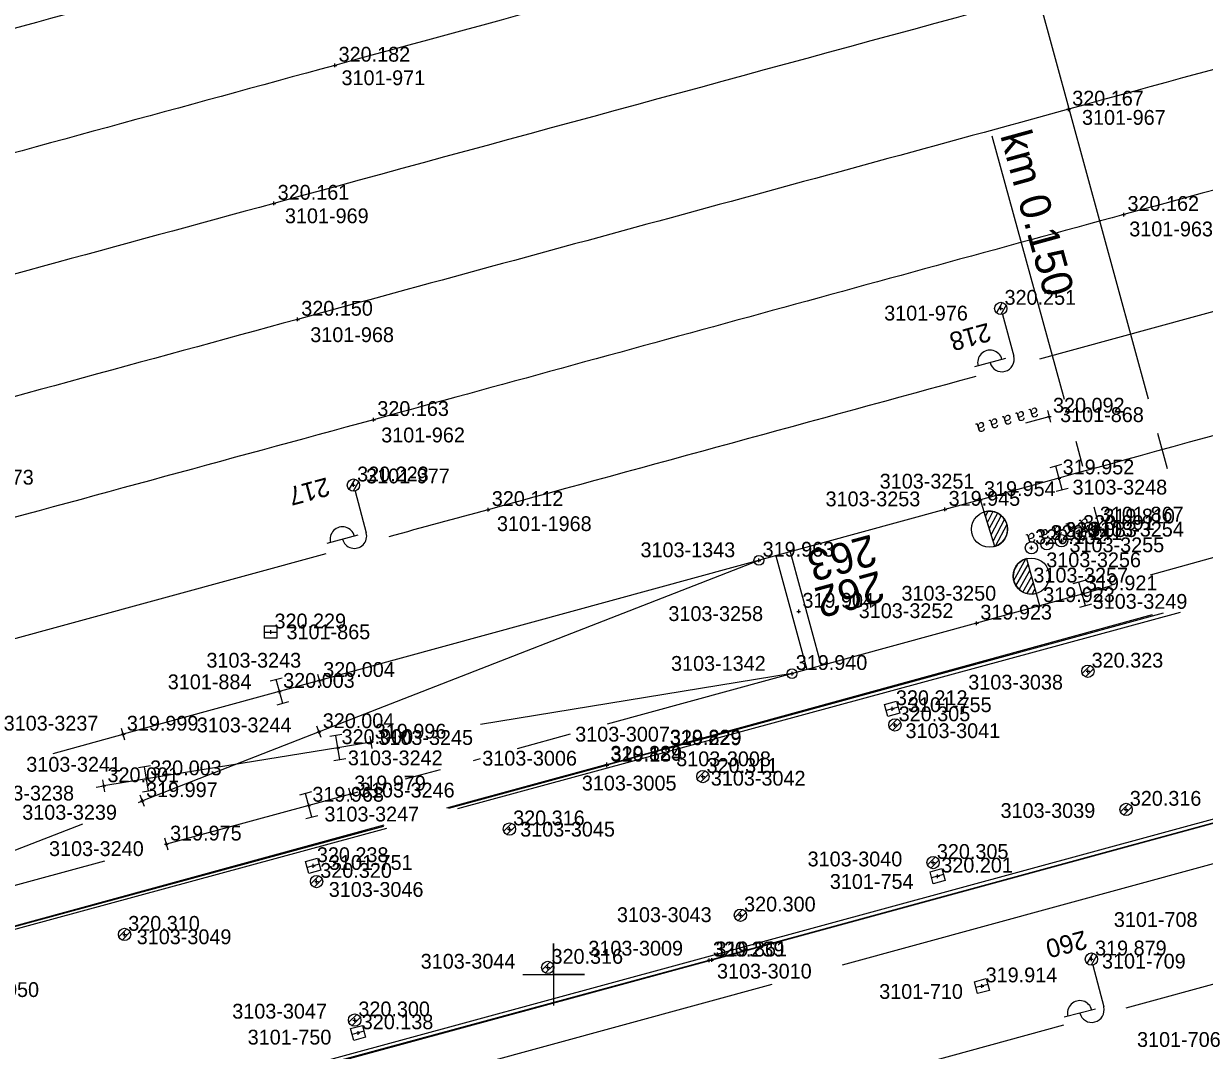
# Model space of a CAD drawing. Extents: x -821875 to -821475, y -1070280 to -1069975.
# Drawn here: x -821621.48 to -821573.63, y -1070203.07 to -1070161.48 of the extents above; entities that cross this region are included whole.
import ezdxf

# ---------------------------------------------------------------- set-up
doc = ezdxf.new("R2010")
doc.units = 0
for name, color, linetype in [('Vrstva 1', 7, 'Continuous'), ('Vrstva 11', 7, 'Continuous'), ('Vrstva 14', 7, 'Continuous'), ('Vrstva 2', 7, 'Continuous'), ('Vrstva 25', 7, 'Continuous'), ('Vrstva 28', 7, 'Continuous'), ('Vrstva 3', 7, 'Continuous'), ('Vrstva 36', 7, 'Continuous'), ('Vrstva 43', 7, 'Continuous'), ('Vrstva 6', 7, 'Continuous'), ('Vrstva 60', 7, 'Continuous'), ('Vrstva 61', 7, 'Continuous'), ('Vrstva 7', 7, 'Continuous')]:
    doc.layers.add(name, color=color, linetype=linetype)

# ---------------------------------------------------------------- blocks, each defined once
blk = doc.blocks.new('BOD')
at = {"layer": 'Vrstva 3'}
for p, q in [((-0.15, 0), (0.15, 0)), ((0, -0.15), (0, 0.15))]:
    blk.add_line(p, q, dxfattribs=at)

msp = doc.modelspace()

# ---------------------------------------------------------------- linework, layer by layer
at = {"layer": 'Vrstva 1'}
for p, q in [((-821556.332, -1070168.522), (-821580.315, -1070175.074)), ((-821609.224, -1070182.961), (-821633.113, -1070189.465)), ((-821577.392, -1070184.259), (-821578.582, -1070184.587)), ((-821552.91, -1070194.831), (-821576.812, -1070201.363)), ((-821579.336, -1070202.053), (-821600.342, -1070207.794))]:
    msp.add_line(p, q, dxfattribs=at)
for points in [[(-821579.522, -1070179.891), (-821582.708, -1070180.77)], [(-821578.582, -1070184.587), (-821580.31, -1070185.065)], [(-821609.487, -1070188.094), (-821617.444, -1070190.271)], [(-821547.636, -1070188.511), (-821567.889, -1070194.046), (-821588.306, -1070199.621)], [(-821609.506, -1070190.171), (-821616.664, -1070192.965)], [(-821607.396, -1070190.595), (-821608.744, -1070190.817), (-821616.5, -1070192.079), (-821618.229, -1070192.359)], [(-821608.229, -1070192.695), (-821609.926, -1070193.15), (-821615.692, -1070194.722)], [(-821601.25, -1070200), (-821600, -1070200), (-821600, -1070198.75), (-821600, -1070200), (-821598.75, -1070200), (-821600, -1070200), (-821600, -1070201.25)], [(-821591.155, -1070200.399), (-821624.302, -1070209.451)]]:
    msp.add_lwpolyline(points, dxfattribs=at)
for points in [[(-821515.135, -1070116.801), (-821528.933, -1070119.148), (-821545.007, -1070122.191), (-821565.452, -1070126.847), (-821593.911, -1070134.524), (-821616.729, -1070140.773), (-821646.681, -1070148.977), (-821681.98, -1070158.691), (-821694.065, -1070162.076), (-821706.535, -1070165.88), (-821718.507, -1070169.937)], [(-821540.596, -1070125.428), (-821552.18, -1070128.307), (-821562.458, -1070130.974), (-821571.2, -1070133.262), (-821591.887, -1070138.848), (-821628.102, -1070148.713), (-821679.285, -1070162.663)], [(-821540.784, -1070127.42), (-821561.358, -1070134.748), (-821573.215, -1070138.464), (-821586.824, -1070142.326), (-821602.341, -1070146.553), (-821645.37, -1070158.257), (-821677.113, -1070166.912)], [(-821500, -1070129.211), (-821517.764, -1070133.43), (-821543.081, -1070140.233), (-821582.867, -1070151.05), (-821612.032, -1070158.997), (-821647.71, -1070168.745)], [(-821500, -1070134.157), (-821525.227, -1070140.424), (-821545.665, -1070145.962), (-821584.89, -1070156.649), (-821608.863, -1070163.173), (-821645.742, -1070173.228), (-821684.141, -1070183.689)], [(-821500, -1070139.002), (-821505.719, -1070140.359), (-821526.796, -1070145.75), (-821547.362, -1070151.333), (-821583.687, -1070161.245), (-821611.332, -1070168.765), (-821648.899, -1070179.006), (-821680.4, -1070187.609), (-821711.133, -1070195.974)], [(-821500, -1070143.947), (-821500.602, -1070144.082), (-821526.98, -1070150.62), (-821544.477, -1070155.432), (-821558.026, -1070159.151), (-821579.135, -1070164.951), (-821610.376, -1070173.463), (-821647.463, -1070183.595), (-821678.921, -1070192.191), (-821710.276, -1070200.761)], [(-821500, -1070148.817), (-821511.77, -1070151.622), (-821530.609, -1070156.564), (-821556.604, -1070163.701), (-821576.895, -1070169.217), (-821607.294, -1070177.525), (-821643.435, -1070187.343), (-821669.656, -1070194.488)], [(-821500, -1070158.612), (-821502.104, -1070159.113), (-821527.988, -1070165.772), (-821558.427, -1070174.094), (-821579.522, -1070179.891)], [(-821582.886, -1070175.776), (-821602.655, -1070181.171), (-821606.681, -1070182.268)], [(-821558.309, -1070178.995), (-821560.253, -1070179.53), (-821575.821, -1070183.825)]]:
    msp.add_spline(points, degree=3, dxfattribs=at)
at = {"layer": 'Vrstva 11'}
for p, q in [((-821583.56, -1070148.661), (-821575.906, -1070176.676)), ((-821575.525, -1070178.071), (-821575.135, -1070179.497))]:
    msp.add_line(p, q, dxfattribs=at)
at = {"layer": 'Vrstva 14'}
for p, q in [((-821574.615, -1070185.337), (-821603.891, -1070193.295)), ((-821575.743, -1070185.432), (-821595.438, -1070190.834)), ((-821595.436, -1070190.859), (-821575.284, -1070185.343)), ((-821626.102, -1070208.071), (-821552.45, -1070188.031)), ((-821597.846, -1070191.49), (-821595.438, -1070190.834)), ((-821595.436, -1070190.859), (-821597.841, -1070191.525)), ((-821597.846, -1070191.49), (-821604.336, -1070193.26)), ((-821604.241, -1070193.266), (-821597.841, -1070191.525)), ((-821631.968, -1070200.811), (-821606.881, -1070193.985)), ((-821606.775, -1070194.079), (-821629.002, -1070200.121)), ((-821606.885, -1070193.956), (-821628.981, -1070199.983))]:
    msp.add_line(p, q, dxfattribs=at)
for points in [[(-821593.697, -1070199.421), (-821552.369, -1070188.152)], [(-821552.524, -1070188.23), (-821593.592, -1070199.416)], [(-821625.477, -1070208.02), (-821593.697, -1070199.421)], [(-821593.592, -1070199.416), (-821624.886, -1070207.92)]]:
    msp.add_lwpolyline(points, dxfattribs=at)
at = {"layer": 'Vrstva 2'}
for p, q in [((-821582.554, -1070181.261), (-821582.708, -1070180.77)), ((-821582.121, -1070182.659), (-821582.554, -1070181.261)), ((-821582.121, -1070182.664), (-821582.554, -1070181.266)), ((-821582.399, -1070181.237), (-821582.502, -1070181.432)), ((-821582.196, -1070181.249), (-821582.424, -1070181.683)), ((-821582.018, -1070181.308), (-821582.347, -1070181.932)), ((-821581.862, -1070181.409), (-821582.27, -1070182.182)), ((-821581.73, -1070181.555), (-821582.192, -1070182.433)), ((-821581.633, -1070181.769), (-821582.101, -1070182.657)), ((-821581.636, -1070182.169), (-821581.773, -1070182.431)), ((-821582.12, -1070182.664), (-821582.121, -1070182.664)), ((-821581.354, -1070184.034), (-821580.859, -1070183.161)), ((-821580.84, -1070183.154), (-821580.449, -1070184.565)), ((-821580.84, -1070183.154), (-821580.84, -1070183.154)), ((-821580.84, -1070183.159), (-821580.449, -1070184.569)), ((-821581.339, -1070183.634), (-821581.194, -1070183.376)), ((-821581.263, -1070184.25), (-821580.775, -1070183.387)), ((-821581.136, -1070184.401), (-821580.705, -1070183.64)), ((-821580.983, -1070184.506), (-821580.636, -1070183.892)), ((-821580.807, -1070184.571), (-821580.566, -1070184.144)), ((-821580.605, -1070184.589), (-821580.496, -1070184.397)), ((-821580.449, -1070184.57), (-821580.31, -1070185.065)), ((-821609.421, -1070188.335), (-821609.553, -1070187.853)), ((-821617.378, -1070190.512), (-821617.51, -1070190.03)), ((-821609.415, -1070190.404), (-821609.597, -1070189.938)), ((-821607.355, -1070190.842), (-821607.437, -1070190.348)), ((-821618.189, -1070192.606), (-821618.269, -1070192.112)), ((-821616.573, -1070193.198), (-821616.755, -1070192.732)), ((-821608.164, -1070192.937), (-821608.294, -1070192.453)), ((-821615.626, -1070194.963), (-821615.758, -1070194.481))]:
    msp.add_line(p, q, dxfattribs=at)
for points in [[(-821582.708, -1070180.77), (-821584.144, -1070181.163), (-821609.487, -1070188.094)], [(-821591.681, -1070183.224), (-821609.506, -1070190.171)], [(-821580.31, -1070185.065), (-821582.857, -1070185.771), (-821597.833, -1070189.858)], [(-821590.338, -1070187.813), (-821602.968, -1070189.873)], [(-821620.274, -1070191.041), (-821617.444, -1070190.271)], [(-821599.331, -1070190.267), (-821601.474, -1070190.852)], [(-821607.3, -1070190.579), (-821607.396, -1070190.595)], [(-821602.982, -1070191.263), (-821603.26, -1070191.339)], [(-821604.602, -1070191.705), (-821606.019, -1070192.092)], [(-821618.531, -1070192.408), (-821618.229, -1070192.359)], [(-821607.931, -1070192.614), (-821608.229, -1070192.695)], [(-821616.82, -1070193.026), (-821616.664, -1070192.965)], [(-821634.061, -1070199.709), (-821619.083, -1070193.903)], [(-821645.282, -1070202.79), (-821641.649, -1070201.769), (-821618.187, -1070195.399)]]:
    msp.add_lwpolyline(points, dxfattribs=at)
for centre, radius in [((-821582.337, -1070181.964), 0.731), ((-821591.681, -1070183.224), 0.2), ((-821580.644, -1070183.86), 0.731), ((-821590.338, -1070187.813), 0.2)]:
    msp.add_circle(centre, radius, dxfattribs=at)
for centre, start, end in [((-821582.337, -1070181.964), 287.2606, 107.2214), ((-821580.644, -1070183.86), 105.4987, 285.4595)]:
    msp.add_arc(centre, 0.732, start, end, dxfattribs=at)
at = {"layer": 'Vrstva 25'}
for p, q in [((-821581.821, -1070172.779), (-821582.057, -1070173.194)), ((-821581.667, -1070172.888), (-821581.884, -1070173.269)), ((-821581.812, -1070173.262), (-821581.351, -1070174.95)), ((-821581.688, -1070175.042), (-821582.942, -1070175.385)), ((-821608.054, -1070179.935), (-821608.293, -1070180.35)), ((-821607.901, -1070180.044), (-821608.121, -1070180.426)), ((-821608.047, -1070180.419), (-821607.591, -1070182.108)), ((-821607.928, -1070182.199), (-821609.184, -1070182.539)), ((-821578.148, -1070199.136), (-821578.391, -1070199.549)), ((-821577.996, -1070199.247), (-821578.219, -1070199.627)), ((-821578.146, -1070199.62), (-821577.708, -1070201.314)), ((-821578.047, -1070201.402), (-821579.306, -1070201.728))]:
    msp.add_line(p, q, dxfattribs=at)
for centre in [(-821581.878, -1070173.021), (-821581.878, -1070173.021), (-821608.113, -1070180.177), (-821608.113, -1070180.177), (-821578.209, -1070199.378), (-821578.209, -1070199.378)]:
    msp.add_circle(centre, 0.25, dxfattribs=at)
for centre, start, end in [((-821582.317, -1070175.208), 14.5886, 195.9938), ((-821581.833, -1070175.082), 195.2912, 15.2912), ((-821608.558, -1070182.363), 14.434, 195.8391), ((-821608.073, -1070182.238), 195.1366, 15.1366), ((-821578.678, -1070201.559), 13.8051, 195.2103), ((-821578.192, -1070201.439), 194.5077, 14.5077)]:
    msp.add_arc(centre, 0.5, start, end, dxfattribs=at)
at = {"layer": 'Vrstva 28'}
for p, q in [((-821578.719, -1070182.143), (-821578.669, -1070182.143)), ((-821580.663, -1070182.715), (-821580.613, -1070182.715)), ((-821580.036, -1070182.548), (-821579.986, -1070182.548)), ((-821579.444, -1070182.428), (-821579.394, -1070182.428))]:
    msp.add_line(p, q, dxfattribs=at)
for centre in [(-821579.419, -1070182.428), (-821578.694, -1070182.143), (-821580.638, -1070182.715), (-821580.011, -1070182.548)]:
    msp.add_circle(centre, 0.25, dxfattribs=at)
at = {"layer": 'Vrstva 3'}
for p, q in [((-821579.413, -1070179.342), (-821579.896, -1070179.475)), ((-821579.389, -1070180.373), (-821579.655, -1070179.409)), ((-821579.148, -1070180.307), (-821579.631, -1070180.44)), ((-821578.474, -1070184.039), (-821578.956, -1070184.172)), ((-821578.449, -1070185.069), (-821578.715, -1070184.105)), ((-821578.208, -1070185.002), (-821578.69, -1070185.135)), ((-821611.002, -1070187.99), (-821611.484, -1070188.121)), ((-821610.979, -1070189.021), (-821611.243, -1070188.055)), ((-821610.738, -1070188.955), (-821611.22, -1070189.086)), ((-821608.578, -1070190.283), (-821609.071, -1070190.364)), ((-821608.663, -1070191.31), (-821608.825, -1070190.324)), ((-821608.417, -1070191.27), (-821608.91, -1070191.351)), ((-821616.334, -1070191.546), (-821616.827, -1070191.626)), ((-821616.42, -1070192.572), (-821616.58, -1070191.586)), ((-821616.173, -1070192.532), (-821616.666, -1070192.612)), ((-821609.815, -1070192.602), (-821610.298, -1070192.733)), ((-821609.796, -1070193.632), (-821610.056, -1070192.668)), ((-821609.554, -1070193.567), (-821610.037, -1070193.698))]:
    msp.add_line(p, q, dxfattribs=at)
at = {"layer": 'Vrstva 36'}
for p, q in [((-821578.578, -1070187.81), (-821578.256, -1070187.487)), ((-821578.448, -1070187.945), (-821578.121, -1070187.618)), ((-821586.398, -1070189.982), (-821586.074, -1070189.659)), ((-821586.268, -1070190.117), (-821585.94, -1070189.79)), ((-821594.182, -1070192.076), (-821593.858, -1070191.753)), ((-821594.052, -1070192.211), (-821593.724, -1070191.884)), ((-821577.032, -1070193.406), (-821576.71, -1070193.083)), ((-821576.902, -1070193.541), (-821576.575, -1070193.214)), ((-821602.02, -1070194.199), (-821601.698, -1070193.876)), ((-821601.89, -1070194.334), (-821601.563, -1070194.006)), ((-821584.85, -1070195.558), (-821584.528, -1070195.235)), ((-821584.72, -1070195.693), (-821584.393, -1070195.366)), ((-821609.836, -1070196.325), (-821609.514, -1070196.002)), ((-821609.706, -1070196.46), (-821609.379, -1070196.132)), ((-821592.662, -1070197.689), (-821592.34, -1070197.366)), ((-821592.532, -1070197.824), (-821592.205, -1070197.496)), ((-821617.618, -1070198.471), (-821617.296, -1070198.148)), ((-821617.488, -1070198.606), (-821617.161, -1070198.278)), ((-821600.466, -1070199.808), (-821600.142, -1070199.485)), ((-821600.336, -1070199.943), (-821600.008, -1070199.616)), ((-821608.292, -1070201.937), (-821607.97, -1070201.614)), ((-821608.162, -1070202.072), (-821607.835, -1070201.744))]:
    msp.add_line(p, q, dxfattribs=at)
for centre in [(-821578.348, -1070187.718), (-821586.167, -1070189.89), (-821593.951, -1070191.984), (-821576.802, -1070193.314), (-821601.79, -1070194.107), (-821584.62, -1070195.466), (-821609.606, -1070196.233), (-821592.432, -1070197.597), (-821617.388, -1070198.379), (-821600.235, -1070199.716), (-821608.062, -1070201.845)]:
    msp.add_circle(centre, 0.25, dxfattribs=at)
at = {"layer": 'Vrstva 43'}
for points in [[(-821611.711, -1070186.131), (-821611.711, -1070185.881), (-821611.211, -1070185.881), (-821611.211, -1070186.381), (-821611.711, -1070186.381), (-821611.711, -1070186.131), (-821611.211, -1070186.131)], [(-821586.039, -1070189.174), (-821585.973, -1070189.414), (-821586.455, -1070189.546), (-821586.587, -1070189.064), (-821586.105, -1070188.932), (-821586.039, -1070189.174), (-821586.521, -1070189.304)], [(-821609.502, -1070195.532), (-821609.436, -1070195.774), (-821609.919, -1070195.905), (-821610.05, -1070195.422), (-821609.567, -1070195.291), (-821609.502, -1070195.532), (-821609.984, -1070195.664)], [(-821584.199, -1070195.954), (-821584.133, -1070196.194), (-821584.615, -1070196.326), (-821584.747, -1070195.844), (-821584.265, -1070195.712), (-821584.199, -1070195.954), (-821584.681, -1070196.084)], [(-821582.402, -1070200.402), (-821582.336, -1070200.642), (-821582.818, -1070200.774), (-821582.95, -1070200.292), (-821582.468, -1070200.16), (-821582.402, -1070200.402), (-821582.884, -1070200.532)], [(-821607.684, -1070202.3), (-821607.618, -1070202.541), (-821608.1, -1070202.673), (-821608.232, -1070202.191), (-821607.75, -1070202.059), (-821607.684, -1070202.3), (-821608.166, -1070202.432)]]:
    msp.add_lwpolyline(points, dxfattribs=at)
at = {"layer": 'Vrstva 6'}
for p, q in [((-821579.298, -1070176.704), (-821582.233, -1070166.036)), ((-821580.869, -1070177.65), (-821579.914, -1070177.39)), ((-821579.849, -1070177.631), (-821579.979, -1070177.149)), ((-821578.552, -1070179.416), (-821578.829, -1070178.41)), ((-821577.874, -1070181.88), (-821578.095, -1070181.075)), ((-821577.809, -1070182.121), (-821577.939, -1070181.639)), ((-821578.829, -1070182.139), (-821577.874, -1070181.88))]:
    msp.add_line(p, q, dxfattribs=at)
at = {"layer": 'Vrstva 7'}
for p, q in [((-821590.996, -1070183.037), (-821589.736, -1070187.648)), ((-821590.417, -1070182.879), (-821589.157, -1070187.49))]:
    msp.add_line(p, q, dxfattribs=at)

# ---------------------------------------------------------------- block references
at = {"layer": 'Vrstva 60', "xscale": 0.5, "yscale": 0.5}
for p in [(-821608.863, -1070163.173), (-821579.135, -1070164.951), (-821611.332, -1070168.765), (-821576.895, -1070169.217), (-821581.878, -1070173.021), (-821610.376, -1070173.463), (-821607.294, -1070177.525), (-821579.914, -1070177.39), (-821579.522, -1070179.891), (-821608.113, -1070180.177), (-821582.708, -1070180.77), (-821602.655, -1070181.171), (-821584.144, -1070181.163), (-821578.694, -1070182.143), (-821577.874, -1070181.88), (-821580.638, -1070182.715), (-821580.011, -1070182.548), (-821579.419, -1070182.428), (-821591.681, -1070183.224), (-821578.582, -1070184.587), (-821580.31, -1070185.065), (-821590.068, -1070185.293), (-821611.461, -1070186.131), (-821582.857, -1070185.771), (-821590.338, -1070187.813), (-821578.348, -1070187.718), (-821611.111, -1070188.538), (-821609.487, -1070188.094), (-821586.28, -1070189.239), (-821586.167, -1070189.89), (-821617.444, -1070190.271), (-821609.506, -1070190.171), (-821608.744, -1070190.817), (-821607.396, -1070190.595), (-821595.438, -1070190.834), (-821595.436, -1070190.859), (-821597.846, -1070191.49), (-821597.841, -1070191.525), (-821618.229, -1070192.359), (-821616.5, -1070192.079), (-821593.951, -1070191.984), (-821608.229, -1070192.695), (-821616.664, -1070192.965), (-821609.926, -1070193.15), (-821576.802, -1070193.314), (-821601.79, -1070194.107), (-821615.692, -1070194.722), (-821609.743, -1070195.598), (-821584.62, -1070195.466), (-821584.44, -1070196.019), (-821609.606, -1070196.233), (-821592.432, -1070197.597), (-821617.388, -1070198.379), (-821593.697, -1070199.421), (-821593.592, -1070199.416), (-821578.209, -1070199.378), (-821600.235, -1070199.716), (-821582.643, -1070200.467), (-821608.062, -1070201.845), (-821607.925, -1070202.366)]:
    msp.add_blockref('BOD', p, dxfattribs=at)

# ---------------------------------------------------------------- texts
at = {"layer": 'Vrstva 2'}
for s, rotation, p in [('263', 195.1866, (-821587.123, -1070182.165)), ('262', 195.2643, (-821586.813, -1070183.634))]:
    msp.add_text(s, height=1.25, rotation=rotation, dxfattribs=at).set_placement(p)
at = {"layer": 'Vrstva 25'}
for s, rotation, p in [('218', 195.2911, (-821582.404, -1070173.594)), ('217', 195.1365, (-821609.197, -1070179.856)), ('260', 194.5078, (-821578.497, -1070198.205))]:
    msp.add_text(s, height=0.75, rotation=rotation, dxfattribs=at).set_placement(p)
at = {"layer": 'Vrstva 6'}
for s, height, rotation, p in [('km 0.150', 1.25, 285.3817, (-821581.911, -1070166.005)), ('  a a a a a', 0.5, 195.2364, (-821580.045, -1070176.907)), ('  a a a a a', 0.5, 195.2032, (-821578.004, -1070181.397))]:
    msp.add_text(s, height=height, rotation=rotation, dxfattribs=at).set_placement(p)
at = {"layer": 'Vrstva 60'}
for s, p in [('3101-971', (-821608.596, -1070163.975)), ('3101-967', (-821578.588, -1070165.581)), ('3101-969', (-821610.888, -1070169.567)), ('3101-963', (-821576.673, -1070170.1)), ('3101-976', (-821586.605, -1070173.508)), ('3101-968', (-821609.861, -1070174.383)), ('3101-868', (-821579.475, -1070177.623)), ('3101-962', (-821606.987, -1070178.445)), ('3101-973', (-821624.458, -1070180.156)), ('3101-977', (-821607.598, -1070180.105)), ('3103-3251', (-821586.785, -1070180.317)), ('3103-3248', (-821578.974, -1070180.557)), ('3103-3253', (-821588.979, -1070181.035)), ('3101-867', (-821577.864, -1070181.652)), ('3101-1968', (-821602.296, -1070182.038)), ('3103-3254', (-821578.3, -1070182.261)), ('3103-1343', (-821596.48, -1070183.097)), ('3103-3255', (-821579.095, -1070182.895)), ('3103-3256', (-821580.036, -1070183.503)), ('3103-3257', (-821580.558, -1070184.122)), ('3103-3250', (-821585.904, -1070184.857)), ('3103-3249', (-821578.156, -1070185.187)), ('3103-3258', (-821595.349, -1070185.681)), ('3103-3252', (-821587.636, -1070185.562)), ('3101-865', (-821610.823, -1070186.42)), ('3103-3243', (-821614.069, -1070187.57)), ('3103-1342', (-821595.242, -1070187.699)), ('3101-884', (-821615.636, -1070188.444)), ('3103-3038', (-821583.197, -1070188.459)), ('3101-755', (-821585.642, -1070189.371)), ('3103-3237', (-821622.285, -1070190.12)), ('3103-3244', (-821614.461, -1070190.191)), ('3103-3041', (-821585.741, -1070190.424)), ('3103-3245', (-821607.103, -1070190.701)), ('3103-3007', (-821599.126, -1070190.564)), ('3103-3241', (-821621.369, -1070191.785)), ('3103-3242', (-821608.335, -1070191.525)), ('3103-3006', (-821602.891, -1070191.538)), ('3103-3008', (-821595.032, -1070191.563)), ('3103-3042', (-821593.63, -1070192.349)), ('3103-3246', (-821607.849, -1070192.83)), ('3103-3005', (-821598.857, -1070192.546)), ('3103-3238', (-821623.271, -1070192.952)), ('3103-3239', (-821621.533, -1070193.73)), ('3103-3247', (-821609.288, -1070193.801)), ('3103-3039', (-821581.889, -1070193.658)), ('3103-3045', (-821601.353, -1070194.414)), ('3103-3240', (-821620.447, -1070195.201)), ('3101-751', (-821609.105, -1070195.761)), ('3103-3040', (-821589.708, -1070195.62)), ('3101-754', (-821588.806, -1070196.532)), ('3103-3046', (-821609.112, -1070196.855)), ('3103-3043', (-821597.435, -1070197.877)), ('3101-708', (-821577.298, -1070198.074)), ('3103-3049', (-821616.894, -1070198.772)), ('3103-3009', (-821598.593, -1070199.235)), ('3103-3044', (-821605.386, -1070199.763)), ('3101-709', (-821577.778, -1070199.758)), ('3103-3010', (-821593.379, -1070200.163)), ('3103-3050', (-821624.689, -1070200.911)), ('3101-710', (-821586.806, -1070200.987)), ('3103-3047', (-821613.022, -1070201.787)), ('3101-750', (-821612.398, -1070202.837)), ('3101-706', (-821576.358, -1070202.933))]:
    msp.add_text(s, height=0.6, dxfattribs=at).set_placement(p)
at = {"layer": 'Vrstva 61'}
for s, p in [('320.182', (-821608.713, -1070163.023)), ('320.167', (-821578.985, -1070164.801)), ('320.161', (-821611.182, -1070168.615)), ('320.162', (-821576.745, -1070169.067)), ('320.251', (-821581.728, -1070172.871)), ('320.150', (-821610.226, -1070173.313)), ('320.163', (-821607.144, -1070177.375)), ('320.092', (-821579.764, -1070177.24)), ('319.952', (-821579.372, -1070179.741)), ('320.223', (-821607.963, -1070180.027)), ('319.954', (-821582.558, -1070180.62)), ('320.112', (-821602.505, -1070181.021)), ('319.945', (-821583.994, -1070181.013)), ('319.810', (-821577.724, -1070181.73)), ('320.083', (-821579.269, -1070182.278)), ('320.091', (-821578.544, -1070181.993)), ('320.132', (-821580.488, -1070182.565)), ('320.141', (-821579.861, -1070182.398)), ('319.963', (-821591.531, -1070183.074)), ('319.921', (-821578.432, -1070184.437)), ('319.904', (-821589.918, -1070185.143)), ('319.923', (-821580.16, -1070184.915)), ('319.923', (-821582.707, -1070185.621)), ('320.229', (-821611.311, -1070185.981)), ('320.323', (-821578.198, -1070187.568)), ('320.004', (-821609.337, -1070187.944)), ('319.940', (-821590.188, -1070187.663)), ('320.003', (-821610.961, -1070188.388)), ('320.212', (-821586.13, -1070189.089)), ('320.004', (-821609.356, -1070190.021)), ('320.305', (-821586.017, -1070189.74)), ('319.999', (-821617.294, -1070190.121)), ('319.996', (-821607.246, -1070190.445)), ('320.000', (-821608.594, -1070190.667)), ('319.829', (-821595.288, -1070190.684)), ('320.229', (-821595.286, -1070190.709)), ('319.829', (-821597.696, -1070191.34)), ('320.184', (-821597.691, -1070191.375)), ('320.003', (-821616.35, -1070191.929)), ('320.311', (-821593.801, -1070191.834)), ('320.001', (-821618.079, -1070192.209)), ('319.997', (-821616.514, -1070192.815)), ('319.979', (-821608.079, -1070192.545)), ('319.968', (-821609.776, -1070193)), ('320.316', (-821576.652, -1070193.164)), ('320.316', (-821601.64, -1070193.957)), ('319.975', (-821615.542, -1070194.572)), ('320.238', (-821609.593, -1070195.448)), ('320.305', (-821584.47, -1070195.316)), ('320.320', (-821609.456, -1070196.083)), ('320.201', (-821584.29, -1070195.869)), ('320.300', (-821592.282, -1070197.447)), ('320.310', (-821617.238, -1070198.229)), ('320.316', (-821600.085, -1070199.566)), ('320.239', (-821593.547, -1070199.271)), ('319.861', (-821593.442, -1070199.266)), ('319.879', (-821578.059, -1070199.228)), ('319.914', (-821582.493, -1070200.317)), ('320.300', (-821607.912, -1070201.695)), ('320.138', (-821607.775, -1070202.216))]:
    msp.add_text(s, height=0.6, dxfattribs=at).set_placement(p)

doc.saveas('drawing.dxf')
